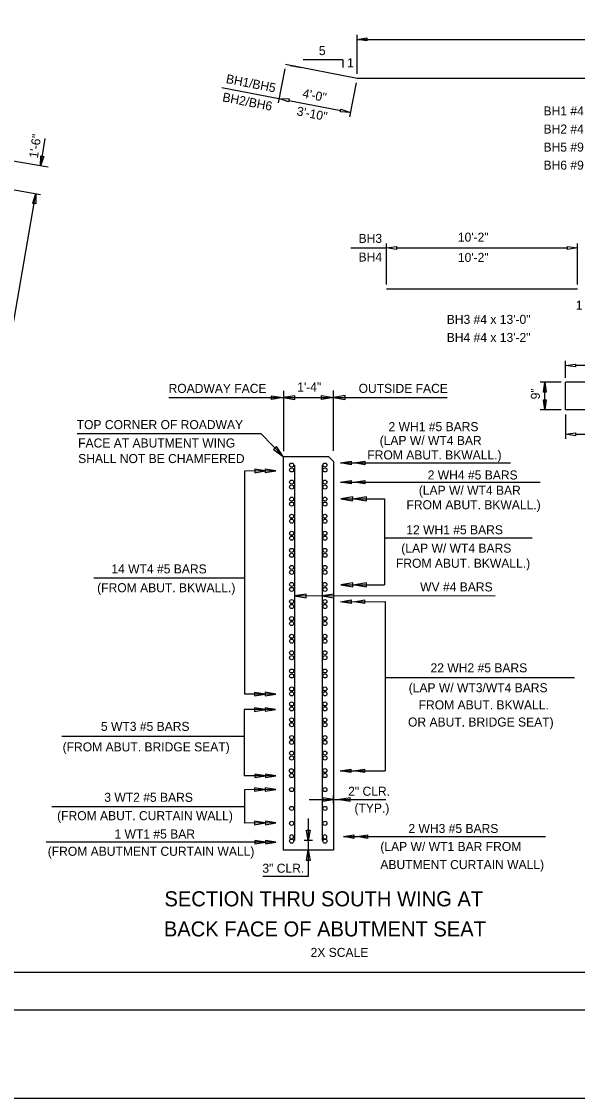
# Model space of a CAD drawing. Extents: x 2146724 to 2153191, y 139029 to 143935.
# Drawn here: x 2147173.7 to 2147203.3, y 143268.4 to 143325.6 of the extents above; entities that cross this region are included whole.
import ezdxf

# ---------------------------------------------------------------- set-up
doc = ezdxf.new("R2010")
doc.units = 0
for name, color, linetype in [('3', 7, 'Continuous'), ('3A', 7, 'Continuous'), ('PR_Bridge_Abutment', 7, 'Continuous'), ('PR_Bridge_Rebar', 7, 'Continuous'), ('PR_Bridge_Reinf', 7, 'Continuous'), ('PR_Dimensions', 7, 'Continuous'), ('PTX_36_LEADER', 7, 'Continuous'), ('SHT_Plot_Shape_Full', 7, 'Continuous'), ('SHT_Plot_Shape_Half', 7, 'Continuous'), ('SHT_Sheet_Border', 7, 'Continuous'), ('T', 7, 'Continuous'), ('T-Title', 7, 'Continuous')]:
    doc.layers.add(name, color=color, linetype=linetype)

# ---------------------------------------------------------------- blocks, each defined once
blk = doc.blocks.new('REINFORCEMENT')
at = {"layer": 'PTX_36_LEADER'}
blk.add_circle((0, 0.106), 0.106, dxfattribs=at)
blk.add_circle((0, 0.106), 0.106, dxfattribs=at)

msp = doc.modelspace()

# ---------------------------------------------------------------- linework, layer by layer
at = {"layer": '3'}
for centre in [(2147188.086, 143301.756), (2147189.858, 143301.756), (2147188.086, 143300.849), (2147189.858, 143300.849), (2147188.086, 143299.942), (2147189.858, 143299.942), (2147188.086, 143299.035), (2147189.858, 143299.035), (2147188.086, 143298.129), (2147189.858, 143298.129), (2147188.086, 143297.222), (2147189.858, 143297.222), (2147188.086, 143296.315), (2147189.858, 143296.315), (2147188.086, 143295.408), (2147189.858, 143295.408), (2147188.086, 143294.501), (2147189.858, 143294.501), (2147188.086, 143293.594), (2147189.858, 143293.594), (2147188.086, 143292.656), (2147189.858, 143292.656), (2147188.086, 143291.78), (2147189.858, 143291.78), (2147188.086, 143290.811), (2147189.858, 143290.811), (2147188.086, 143289.858), (2147189.858, 143289.858), (2147188.086, 143289.059), (2147189.858, 143289.059), (2147188.086, 143288.215), (2147189.858, 143288.215), (2147188.086, 143287.277), (2147189.858, 143287.277), (2147188.086, 143286.447), (2147189.858, 143286.447), (2147188.086, 143285.516), (2147189.858, 143285.516), (2147188.086, 143284.769), (2147189.858, 143284.769), (2147188.086, 143283.769), (2147189.858, 143283.769), (2147188.086, 143282.977), (2147189.858, 143282.977), (2147188.086, 143282.032), (2147189.858, 143282.032)]:
    msp.add_circle(centre, 0.109, dxfattribs=at)
at = {"layer": '3A'}
msp.add_line((2147170.95, 143317.052), (2147174.736, 143316.398), dxfattribs=at)
at = {"layer": 'PR_Bridge_Abutment'}
for p, q in [((2147187.64, 143302.465), (2147187.639, 143281.562)), ((2147187.64, 143302.465), (2147190.054, 143302.465)), ((2147190.054, 143302.465), (2147190.307, 143302.212)), ((2147190.307, 143302.212), (2147190.306, 143281.562)), ((2147187.639, 143281.562), (2147190.306, 143281.562))]:
    msp.add_line(p, q, dxfattribs=at)
at = {"layer": 'PR_Bridge_Rebar'}
for p, q in [((2147191.565, 143322.56), (2147187.768, 143323.297)), ((2147219.155, 143322.56), (2147191.565, 143322.56)), ((2147203.279, 143311.365), (2147193.139, 143311.365)), ((2147208.215, 143306.412), (2147202.652, 143306.412)), ((2147202.652, 143304.946), (2147202.652, 143306.412)), ((2147207.898, 143304.946), (2147202.652, 143304.946))]:
    msp.add_line(p, q, dxfattribs=at)
at = {"layer": 'PR_Bridge_Reinf'}
for p, q in [((2147188.241, 143302.012), (2147188.24, 143282.062)), ((2147189.706, 143302.012), (2147189.705, 143282.062))]:
    msp.add_line(p, q, dxfattribs=at)
at = {"layer": 'PR_Dimensions'}
for p, q in [((2147191.565, 143322.8), (2147191.565, 143324.873)), ((2147191.565, 143324.633), (2147218.627, 143324.633)), ((2147190.801, 143323.55), (2147188.705, 143323.55)), ((2147190.801, 143323.55), (2147190.801, 143323.143)), ((2147187.722, 143323.062), (2147187.372, 143321.258)), ((2147188.003, 143323.252), (2147188.593, 143323.137)), ((2147218.915, 143322.56), (2147194.593, 143322.56)), ((2147184.387, 143322.081), (2147187.417, 143321.493)), ((2147191.52, 143322.325), (2147191.169, 143320.52)), ((2147187.935, 143321.392), (2147190.697, 143320.856)), ((2147174.975, 143319.377), (2147174.751, 143317.913)), ((2147175.151, 143317.844), (2147173.084, 143318.201)), ((2147170.089, 143291.038), (2147174.496, 143316.44)), ((2147191.234, 143313.551), (2147193.139, 143313.551)), ((2147193.139, 143311.605), (2147193.139, 143313.791)), ((2147193.666, 143313.551), (2147202.752, 143313.551)), ((2147203.279, 143311.605), (2147203.279, 143313.791)), ((2147202.652, 143306.652), (2147202.652, 143307.545)), ((2147207.688, 143307.306), (2147203.179, 143307.306)), ((2147202.412, 143306.412), (2147201.306, 143306.412)), ((2147201.546, 143304.946), (2147201.546, 143306.412)), ((2147187.682, 143302.757), (2147187.682, 143305.968)), ((2147190.307, 143302.764), (2147190.307, 143305.975)), ((2147181.569, 143305.604), (2147196.351, 143305.604)), ((2147202.412, 143304.946), (2147201.306, 143304.946)), ((2147202.652, 143304.706), (2147202.652, 143303.41)), ((2147186.478, 143303.678), (2147176.685, 143303.678)), ((2147187.64, 143302.471), (2147186.478, 143303.678)), ((2147203.179, 143303.649), (2147207.371, 143303.649)), ((2147190.692, 143302.13), (2147199.722, 143302.13)), ((2147187.246, 143301.706), (2147185.589, 143301.697)), ((2147185.589, 143301.697), (2147185.589, 143289.848)), ((2147190.692, 143301.103), (2147201.296, 143301.103)), ((2147190.707, 143300.228), (2147193.029, 143300.219)), ((2147193.029, 143300.219), (2147193.031, 143295.65)), ((2147200.88, 143298.132), (2147193.019, 143298.132)), ((2147177.58, 143296.02), (2147185.589, 143296.02)), ((2147190.709, 143295.648), (2147193.03, 143295.65)), ((2147198.91, 143295.052), (2147188.24, 143295.061)), ((2147190.824, 143294.755), (2147193.061, 143294.757)), ((2147193.061, 143294.757), (2147193.061, 143285.771)), ((2147203.115, 143290.717), (2147193.061, 143290.717)), ((2147187.246, 143289.846), (2147185.589, 143289.848)), ((2147187.107, 143289.023), (2147185.568, 143289.025)), ((2147185.568, 143289.025), (2147185.568, 143285.499)), ((2147175.874, 143287.605), (2147185.568, 143287.605)), ((2147190.674, 143285.769), (2147193.061, 143285.771)), ((2147187.252, 143285.5), (2147185.568, 143285.501)), ((2147187.256, 143284.771), (2147185.577, 143284.762)), ((2147185.577, 143284.762), (2147185.577, 143282.986)), ((2147189.02, 143284.246), (2147193.085, 143284.247)), ((2147190.301, 143284.459), (2147190.301, 143284.049)), ((2147175.345, 143283.874), (2147185.577, 143283.874)), ((2147187.256, 143282.995), (2147185.577, 143282.986)), ((2147188.973, 143283.226), (2147188.972, 143280.155)), ((2147187.256, 143281.979), (2147175.043, 143281.979)), ((2147189.192, 143282.062), (2147188.753, 143282.062)), ((2147190.84, 143282.272), (2147201.582, 143282.272)), ((2147188.972, 143280.155), (2147186.554, 143280.156))]:
    msp.add_line(p, q, dxfattribs=at)
for points in [[(2147192.092, 143324.554), (2147191.565, 143324.633), (2147192.092, 143324.712)], [(2147187.92, 143321.315), (2147187.417, 143321.493), (2147187.95, 143321.47)], [(2147190.712, 143320.933), (2147191.215, 143320.755), (2147190.682, 143320.778)], [(2147174.914, 143318.42), (2147174.751, 143317.913), (2147174.758, 143318.446)], [(2147174.334, 143315.923), (2147174.497, 143316.43), (2147174.49, 143315.897)], [(2147174.335, 143315.931), (2147174.496, 143316.44), (2147174.491, 143315.907)], [(2147193.666, 143313.472), (2147193.139, 143313.551), (2147193.666, 143313.63)], [(2147202.752, 143313.63), (2147203.279, 143313.551), (2147202.752, 143313.472)], [(2147203.179, 143307.227), (2147202.652, 143307.306), (2147203.179, 143307.385)], [(2147201.467, 143305.885), (2147201.546, 143306.412), (2147201.625, 143305.885)], [(2147187.015, 143305.491), (2147187.015, 143305.7), (2147187.64, 143305.597)], [(2147188.265, 143305.493), (2147188.265, 143305.701), (2147187.64, 143305.597)], [(2147189.682, 143305.5), (2147189.682, 143305.708), (2147190.307, 143305.604)], [(2147190.931, 143305.498), (2147190.932, 143305.706), (2147190.307, 143305.604)], [(2147201.625, 143305.473), (2147201.546, 143304.946), (2147201.467, 143305.473)], [(2147203.179, 143303.57), (2147202.652, 143303.649), (2147203.179, 143303.729)], [(2147187.282, 143302.994), (2147187.132, 143302.849), (2147187.64, 143302.471)], [(2147186.126, 143301.609), (2147186.686, 143301.703), (2147186.126, 143301.796)], [(2147186.686, 143301.612), (2147187.246, 143301.706), (2147186.686, 143301.799)], [(2147191.252, 143302.036), (2147190.692, 143302.13), (2147191.252, 143302.223)], [(2147191.971, 143302.036), (2147191.411, 143302.13), (2147191.971, 143302.223)], [(2147191.252, 143301.01), (2147190.692, 143301.103), (2147191.252, 143301.196)], [(2147191.971, 143301.01), (2147191.411, 143301.103), (2147191.971, 143301.196)], [(2147191.332, 143300.122), (2147191.333, 143300.33), (2147190.707, 143300.228)], [(2147192.064, 143300.122), (2147192.065, 143300.33), (2147191.439, 143300.228)], [(2147191.333, 143295.542), (2147191.334, 143295.75), (2147190.709, 143295.648)], [(2147192.065, 143295.542), (2147192.066, 143295.75), (2147191.441, 143295.648)], [(2147188.865, 143294.954), (2147188.866, 143295.162), (2147188.24, 143295.061)], [(2147190.33, 143294.952), (2147190.331, 143295.16), (2147189.705, 143295.059)], [(2147191.251, 143294.662), (2147190.691, 143294.756), (2147191.251, 143294.849)], [(2147191.97, 143294.662), (2147191.41, 143294.756), (2147191.97, 143294.849)], [(2147186.121, 143289.75), (2147186.681, 143289.843), (2147186.121, 143289.936)], [(2147186.681, 143289.753), (2147187.241, 143289.846), (2147186.681, 143289.939)], [(2147186.12, 143288.927), (2147186.68, 143289.02), (2147186.12, 143289.114)], [(2147186.68, 143288.93), (2147187.24, 143289.023), (2147186.68, 143289.117)], [(2147191.234, 143285.676), (2147190.674, 143285.769), (2147191.234, 143285.863)], [(2147191.953, 143285.676), (2147191.393, 143285.769), (2147191.953, 143285.863)], [(2147186.132, 143285.404), (2147186.692, 143285.497), (2147186.132, 143285.59)], [(2147186.692, 143285.407), (2147187.252, 143285.5), (2147186.692, 143285.593)], [(2147186.108, 143284.678), (2147186.668, 143284.772), (2147186.108, 143284.865)], [(2147186.689, 143284.678), (2147187.249, 143284.771), (2147186.689, 143284.864)], [(2147189.741, 143284.153), (2147190.301, 143284.246), (2147189.741, 143284.339)], [(2147191.2, 143284.339), (2147190.64, 143284.246), (2147191.2, 143284.153)], [(2147186.115, 143282.903), (2147186.675, 143282.996), (2147186.115, 143283.089)], [(2147186.696, 143282.902), (2147187.256, 143282.995), (2147186.696, 143283.089)], [(2147189.066, 143282.622), (2147188.973, 143282.062), (2147188.879, 143282.622)], [(2147191.4, 143282.178), (2147190.84, 143282.272), (2147191.4, 143282.365)], [(2147192.119, 143282.178), (2147191.559, 143282.272), (2147192.119, 143282.365)], [(2147186.136, 143281.886), (2147186.696, 143281.979), (2147186.136, 143282.072)], [(2147186.696, 143281.886), (2147187.256, 143281.979), (2147186.696, 143282.072)], [(2147188.879, 143281.002), (2147188.972, 143281.562), (2147189.066, 143281.002)]]:
    msp.add_lwpolyline(points, close=True, dxfattribs=at)
msp.add_lwpolyline([(2147191.2, 143284.246), (2147193.091, 143284.246)], dxfattribs=at)
at = {"layer": 'SHT_Plot_Shape_Full'}
msp.add_lwpolyline([(2147114.94, 143364.357), (2147258.94, 143364.357), (2147258.94, 143268.357), (2147114.94, 143268.357)], close=True, dxfattribs=at)
at = {"layer": 'SHT_Plot_Shape_Half'}
msp.add_lwpolyline([(2147121.49, 143361.057), (2147257.49, 143361.057), (2147257.49, 143273.057), (2147121.49, 143273.057)], close=True, dxfattribs=at)
at = {"layer": 'SHT_Sheet_Border'}
msp.add_lwpolyline([(2147255.29, 143275.057), (2147129.29, 143275.057), (2147129.29, 143359.057), (2147255.29, 143359.057)], close=True, dxfattribs=at)

# ---------------------------------------------------------------- block references
at = {"layer": 'PR_Bridge_Reinf', "rotation": 152.99999999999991}
for p in [(2147188.135, 143302.111), (2147189.906, 143302.111), (2147188.135, 143301.205), (2147189.906, 143301.205), (2147188.135, 143300.298), (2147189.906, 143300.298), (2147188.135, 143299.391), (2147189.906, 143299.391), (2147188.135, 143298.484), (2147189.906, 143298.484), (2147188.135, 143297.577), (2147189.906, 143297.577), (2147188.135, 143296.67), (2147189.906, 143296.67), (2147188.135, 143295.763), (2147189.906, 143295.763), (2147188.135, 143294.856), (2147189.906, 143294.856), (2147188.135, 143293.949), (2147189.906, 143293.949), (2147188.135, 143293.011), (2147189.906, 143293.011), (2147188.135, 143292.135), (2147189.906, 143292.135), (2147188.135, 143291.166), (2147189.906, 143291.166), (2147188.135, 143290.213), (2147189.906, 143290.213), (2147188.135, 143289.415), (2147189.906, 143289.415), (2147188.135, 143288.57), (2147189.906, 143288.57), (2147188.135, 143287.632), (2147189.906, 143287.632), (2147188.135, 143286.803), (2147189.906, 143286.803), (2147188.123, 143285.868), (2147189.906, 143285.872)]:
    msp.add_blockref('REINFORCEMENT', p, dxfattribs=at)
at = {"layer": 'PR_Bridge_Reinf', "yscale": -1, "rotation": -152.99999999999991}
for p in [(2147188.135, 143282.157), (2147189.906, 143282.157)]:
    msp.add_blockref('REINFORCEMENT', p, dxfattribs=at)

# ---------------------------------------------------------------- texts
at = {"layer": 'Defpoints'}
msp.add_text('2X SCALE', height=0.48, dxfattribs=at).set_placement((2147189.096, 143275.878))
at = {"layer": 'PR_Dimensions'}
for s, rotation, p in [('BH1/BH5', 349.0095, (2147184.571, 143322.322)), ('4\'-0"', 349.0095, (2147188.637, 143321.549)), ('BH2/BH6', 349.0095, (2147184.382, 143321.348)), ('3\'-10"', 349.0095, (2147188.331, 143320.605)), ('1\'-6"', 81.3025, (2147174.599, 143318.297)), ('BH3', 0, (2147191.647, 143313.822)), ('10\'-2"', 0, (2147196.925, 143313.887)), ('BH4', 0, (2147191.647, 143312.831)), ('10\'-2"', 0, (2147196.925, 143312.811)), ('9"', 90, (2147201.281, 143305.51))]:
    msp.add_text(s, height=0.4792, rotation=rotation, dxfattribs=at).set_placement(p)
at = {"layer": 'T'}
for s, p in [('5', (2147189.537, 143323.8)), ('1', (2147191.038, 143323.153)), ('BH1 #4 x 34\'-5"', (2147201.476, 143320.592)), ('BH2 #4 x 34\'-4"', (2147201.476, 143319.632)), ('BH5 #9 x 34\'-5"', (2147201.476, 143318.672)), ('BH6 #9 x 34\'-4"', (2147201.476, 143317.712)), ('1', (2147203.19, 143310.272)), ('BH3 #4 x 13\'-0"', (2147196.332, 143309.516)), ('BH4 #4 x 13\'-2"', (2147196.332, 143308.556)), ('1\'-4"', (2147188.385, 143305.924)), ('ROADWAY FACE', (2147181.547, 143305.85)), ('OUTSIDE FACE', (2147191.648, 143305.85)), ('TOP CORNER OF ROADWAY', (2147176.665, 143303.924)), ('2 WH1 #5 BARS', (2147193.239, 143303.816)), ('(LAP W/ WT4 BAR ', (2147192.768, 143303.082)), ('FACE AT ABUTMENT WING', (2147176.744, 143302.948)), ('SHALL NOT BE CHAMFERED', (2147176.744, 143302.12)), ('FROM ABUT. BKWALL.)', (2147192.112, 143302.314)), ('2 WH4 #5 BARS', (2147195.319, 143301.248)), ('(LAP W/ WT4 BAR ', (2147194.848, 143300.435)), ('FROM ABUT. BKWALL.)', (2147194.192, 143299.667)), ('12 WH1 #5 BARS', (2147194.181, 143298.335)), ('(LAP W/ WT4 BARS', (2147193.917, 143297.359)), ('14 WT4 #5 BARS', (2147178.509, 143296.257)), ('FROM ABUT. BKWALL.)', (2147193.633, 143296.557)), ('(FROM ABUT. BKWALL.)', (2147177.753, 143295.258)), ('22 WH2 #5 BARS', (2147195.472, 143291.001)), ('(LAP W/ WT3/WT4 BARS', (2147194.309, 143289.944)), ('FROM ABUT. BKWALL.', (2147194.839, 143289.032)), ('5 WT3 #5 BARS', (2147177.953, 143287.888)), ('OR ABUT. BRIDGE SEAT)', (2147194.274, 143288.12)), ('(FROM ABUT. BRIDGE SEAT)', (2147175.918, 143286.799)), ('2" CLR.', (2147191.093, 143284.442)), ('3 WT2 #5 BARS', (2147178.133, 143284.12)), ('(TYP.)', (2147191.427, 143283.547)), ('(FROM ABUT. CURTAIN WALL)', (2147175.625, 143283.144)), ('2 WH3 #5 BARS', (2147194.295, 143282.463)), ('1 WT1 #5 BAR', (2147178.674, 143282.17)), ('(LAP W/ WT1 BAR FROM', (2147192.804, 143281.505)), ('(FROM ABUTMENT CURTAIN WALL)', (2147175.126, 143281.251)), ('3" CLR.', (2147186.534, 143280.351)), ('ABUTMENT CURTAIN WALL)', (2147192.804, 143280.545))]:
    msp.add_text(s, height=0.48, dxfattribs=at).set_placement(p)
msp.add_text('WV #4 BARS', height=0.48, rotation=359.9523, dxfattribs=at).set_placement((2147194.917, 143295.303))
at = {"layer": 'T-Title'}
for s, p in [('SECTION THRU SOUTH WING AT', (2147181.329, 143278.566)), ('BACK FACE OF ABUTMENT SEAT', (2147181.298, 143276.966))]:
    msp.add_text(s, height=0.8, dxfattribs=at).set_placement(p)

doc.saveas('drawing.dxf')
